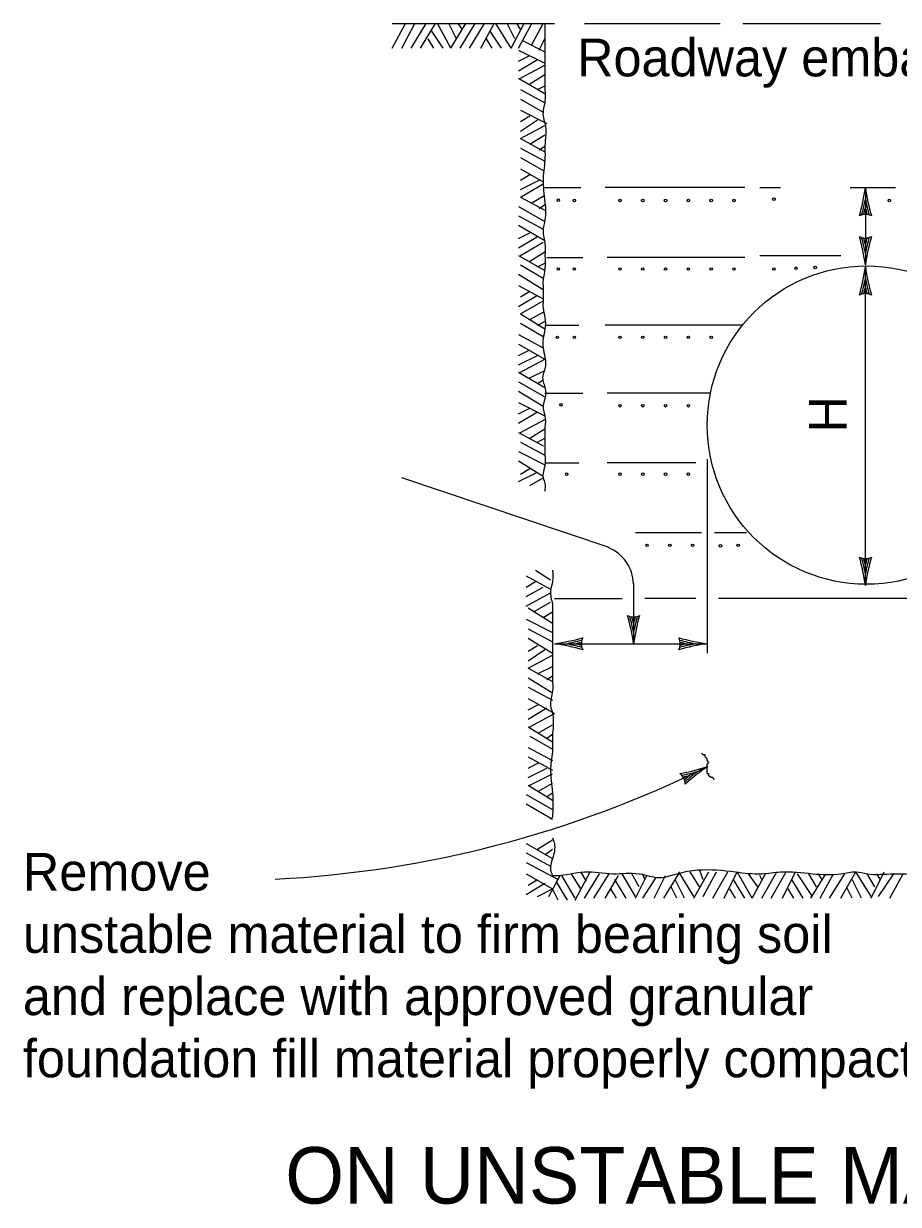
# Model space of a CAD drawing. Extents: x 0 to 390, y 0 to 265.
# Drawn here: x 170.5 to 216.9, y 109.5 to 172.1 of the extents above; entities that cross this region are included whole.
import ezdxf

# ---------------------------------------------------------------- set-up
doc = ezdxf.new("R2010")
doc.units = 0
doc.layers.add('D_Details', color=7, linetype='Continuous')

msp = doc.modelspace()

# ---------------------------------------------------------------- linework, layer by layer
at = {"layer": 'D_Details'}
for p, q in [((190.054, 170.801), (190.754, 172.101)), ((190.054, 172.101), (198.154, 172.101)), ((190.554, 170.801), (191.254, 172.101)), ((191.054, 170.801), (191.854, 172.101)), ((191.554, 170.801), (192.354, 172.101)), ((192.754, 170.801), (192.154, 171.701)), ((193.154, 170.801), (192.454, 172.101)), ((193.454, 171.301), (193.054, 172.101)), ((193.154, 170.801), (193.954, 172.101)), ((193.754, 171.801), (193.554, 172.101)), ((193.654, 170.801), (194.454, 172.101)), ((194.154, 170.801), (194.954, 172.101)), ((194.754, 170.801), (195.454, 172.101)), ((195.854, 170.801), (195.254, 171.701)), ((196.354, 170.801), (195.554, 172.101)), ((196.554, 171.301), (196.154, 172.101)), ((196.354, 170.801), (197.054, 172.101)), ((196.854, 171.801), (196.654, 172.101)), ((196.754, 170.801), (197.454, 172.101)), ((197.454, 171.001), (198.054, 172.101)), ((198.154, 172.101), (198.654, 172.101)), ((200.254, 172.101), (207.454, 172.101)), ((208.654, 172.101), (215.954, 172.101)), ((192.254, 170.801), (191.954, 171.301)), ((195.354, 170.801), (195.054, 171.301)), ((196.954, 171.201), (198.154, 170.601)), ((197.854, 170.701), (198.154, 171.301)), ((198.154, 171.201), (198.154, 171.201)), ((198.154, 171.201), (198.154, 171.201)), ((196.754, 170.701), (198.154, 170.001)), ((196.754, 170.101), (197.354, 170.401)), ((198.254, 171.001), (198.254, 171.001)), ((196.754, 169.601), (197.754, 170.201)), ((196.854, 169.201), (198.154, 169.901)), ((196.754, 169.201), (198.154, 168.401)), ((197.354, 168.901), (198.154, 169.401)), ((196.854, 168.601), (198.154, 167.901)), ((197.754, 168.601), (198.154, 168.801)), ((196.854, 168.101), (198.054, 167.401)), ((196.854, 167.501), (198.254, 166.801)), ((196.854, 166.901), (197.354, 167.201)), ((196.854, 166.401), (197.754, 167.001)), ((196.854, 166.001), (198.154, 166.701)), ((196.854, 166.001), (198.154, 165.301)), ((197.354, 165.701), (198.154, 166.201)), ((196.854, 165.501), (198.154, 164.801)), ((197.854, 165.401), (198.154, 165.601)), ((196.854, 165.001), (198.054, 164.301)), ((196.854, 164.401), (198.054, 163.701)), ((196.854, 163.801), (197.354, 164.101)), ((196.854, 163.301), (197.854, 163.801)), ((196.854, 162.901), (198.054, 163.601)), ((196.854, 162.901), (198.154, 162.201)), ((197.454, 162.601), (198.154, 163.001)), ((198.154, 163.401), (200.054, 163.401)), ((208.754, 163.401), (201.354, 163.401)), ((209.554, 163.401), (210.654, 163.401)), ((214.354, 163.401), (216.754, 163.401)), ((215.154, 163.401), (215.154, 159.301)), ((196.754, 162.401), (198.154, 161.601)), ((197.854, 162.301), (198.154, 162.501)), ((196.754, 161.901), (198.054, 161.201)), ((198.154, 162.201), (198.154, 162.201)), ((198.154, 162.201), (198.154, 162.201)), ((196.754, 161.401), (198.154, 160.601)), ((196.754, 160.701), (197.354, 161.001)), ((196.754, 160.201), (197.754, 160.801)), ((196.854, 159.801), (198.054, 160.501)), ((196.754, 159.801), (198.154, 159.001)), ((197.354, 159.501), (198.154, 160.001)), ((209.554, 159.801), (213.854, 159.801)), ((196.854, 159.301), (198.054, 158.601)), ((197.754, 159.201), (198.154, 159.401)), ((198.254, 159.701), (200.154, 159.701)), ((208.754, 159.701), (201.454, 159.701)), ((215.154, 142.301), (215.154, 159.201)), ((196.754, 158.801), (198.054, 158.001)), ((196.754, 158.201), (198.054, 157.501)), ((196.854, 157.601), (197.354, 157.901)), ((196.754, 157.101), (197.754, 157.701)), ((196.854, 156.701), (198.054, 157.401)), ((196.854, 156.701), (198.154, 155.901)), ((197.354, 156.401), (198.054, 156.801)), ((196.854, 156.201), (198.054, 155.501)), ((197.754, 156.101), (198.154, 156.301)), ((198.154, 156.101), (199.954, 156.101)), ((208.654, 156.101), (201.354, 156.101)), ((196.754, 155.601), (198.054, 154.901)), ((196.754, 155.101), (198.154, 154.301)), ((196.754, 154.501), (197.354, 154.801)), ((196.754, 154.001), (197.754, 154.501)), ((196.854, 153.601), (198.154, 154.301)), ((196.754, 153.601), (198.154, 152.801)), ((197.354, 153.301), (198.154, 153.701)), ((196.754, 153.101), (198.154, 152.301)), ((197.754, 153.001), (198.054, 153.201)), ((196.754, 152.601), (198.054, 151.801)), ((198.154, 152.801), (198.154, 152.801)), ((198.154, 152.501), (200.154, 152.501)), ((206.954, 152.501), (201.454, 152.501)), ((196.754, 152.001), (198.154, 151.301)), ((196.754, 151.401), (197.354, 151.701)), ((196.754, 150.901), (197.754, 151.501)), ((196.854, 150.401), (198.154, 151.101)), ((196.754, 150.401), (198.054, 149.701)), ((197.354, 150.101), (198.154, 150.601)), ((196.854, 149.901), (198.154, 149.201)), ((197.754, 149.901), (198.154, 150.101)), ((196.754, 149.401), (198.154, 148.701)), ((196.754, 148.901), (198.054, 148.101)), ((196.854, 148.201), (197.354, 148.501)), ((198.154, 148.801), (199.954, 148.801)), ((206.154, 148.801), (201.454, 148.801)), ((206.754, 149.001), (206.754, 138.701)), ((201.554, 144.301), (190.554, 148.001)), ((196.754, 147.801), (197.754, 148.301)), ((197.354, 147.601), (198.054, 148.001)), ((202.954, 145.101), (206.454, 145.101)), ((207.154, 145.101), (208.854, 145.101)), ((198.154, 143.501), (198.154, 143.501)), ((197.654, 143.101), (198.454, 142.601)), ((197.154, 142.801), (198.454, 142.101)), ((197.154, 142.201), (197.654, 142.501)), ((197.154, 141.701), (198.054, 142.201)), ((202.854, 142.401), (202.854, 139.201)), ((197.154, 141.201), (198.454, 141.901)), ((198.654, 141.601), (202.254, 141.601)), ((206.154, 141.601), (203.454, 141.601)), ((232.154, 141.601), (207.354, 141.601)), ((197.254, 141.101), (198.554, 140.301)), ((197.554, 140.901), (198.454, 141.401)), ((197.154, 140.501), (198.554, 139.801)), ((198.054, 140.601), (198.554, 140.901)), ((198.554, 140.501), (198.554, 140.501)), ((197.254, 140.001), (198.554, 139.301)), ((198.654, 140.301), (198.654, 140.301)), ((197.254, 139.501), (198.554, 138.701)), ((197.254, 138.801), (197.754, 139.101)), ((198.654, 139.201), (206.754, 139.201)), ((197.254, 138.301), (198.154, 138.901)), ((197.254, 137.901), (198.554, 138.601)), ((197.254, 137.901), (198.554, 137.201)), ((197.754, 137.601), (198.554, 138.001)), ((197.254, 137.401), (198.554, 136.601)), ((198.254, 137.301), (198.554, 137.501)), ((197.254, 136.901), (198.554, 136.201)), ((197.254, 136.301), (198.654, 135.501)), ((197.254, 135.701), (197.854, 136.001)), ((197.254, 135.201), (198.254, 135.801)), ((197.354, 134.801), (198.654, 135.501)), ((197.254, 134.801), (198.554, 134.001)), ((197.854, 134.501), (198.554, 134.901)), ((197.354, 134.301), (198.554, 133.601)), ((198.254, 134.201), (198.554, 134.401)), ((197.254, 133.701), (198.554, 133.001)), ((197.254, 133.201), (198.554, 132.501)), ((197.254, 132.601), (197.854, 132.901)), ((197.254, 132.101), (198.254, 132.601)), ((197.354, 131.701), (198.554, 132.301)), ((197.254, 131.701), (198.554, 130.901)), ((197.854, 131.401), (198.554, 131.801)), ((197.154, 131.201), (198.554, 130.401)), ((198.254, 131.101), (198.554, 131.301)), ((198.554, 131.001), (198.554, 131.001)), ((197.154, 130.701), (198.554, 129.901)), ((198.554, 130.001), (198.454, 129.901)), ((197.154, 128.601), (198.554, 127.801)), ((197.754, 128.301), (198.554, 128.801)), ((197.154, 128.101), (198.454, 127.401)), ((198.154, 128.001), (198.554, 128.301)), ((197.154, 127.601), (198.854, 126.701)), ((206.554, 126.701), (206.354, 127.201)), ((197.154, 127.001), (198.554, 126.201)), ((197.254, 126.401), (197.754, 126.701)), ((198.354, 125.801), (198.954, 126.901)), ((199.354, 125.601), (198.754, 126.601)), ((199.754, 125.701), (199.054, 126.901)), ((200.054, 126.201), (199.554, 127.001)), ((199.754, 125.601), (200.554, 127.101)), ((200.354, 126.601), (200.054, 127.101)), ((200.254, 125.701), (201.054, 127.001)), ((200.554, 127.101), (200.554, 127.101)), ((200.754, 125.701), (201.554, 127.001)), ((201.354, 125.701), (202.054, 126.901)), ((202.454, 125.701), (201.854, 126.701)), ((202.954, 125.801), (202.254, 127.001)), ((203.154, 126.301), (202.754, 127.001)), ((202.954, 125.701), (203.554, 126.901)), ((203.454, 126.701), (203.354, 127.001)), ((203.354, 125.701), (204.054, 126.801)), ((203.954, 125.701), (204.554, 126.901)), ((204.454, 125.701), (205.254, 127.001)), ((205.554, 125.701), (205.054, 126.701)), ((206.054, 125.801), (205.254, 127.101)), ((206.354, 126.301), (205.854, 127.101)), ((206.054, 125.701), (206.854, 127.101)), ((206.554, 125.801), (207.254, 127.101)), ((207.054, 125.701), (207.854, 127.101)), ((207.654, 125.701), (208.354, 127.101)), ((208.754, 125.701), (208.154, 126.701)), ((209.154, 125.701), (208.354, 127.101)), ((209.454, 126.301), (208.954, 127.001)), ((209.154, 125.701), (209.854, 127.001)), ((209.654, 126.701), (209.554, 126.901)), ((209.654, 125.701), (210.454, 127.101)), ((209.954, 127.101), (209.954, 127.101)), ((210.154, 125.701), (210.954, 127.101)), ((210.754, 125.701), (211.454, 127.101)), ((211.854, 125.701), (211.254, 126.701)), ((212.354, 125.801), (211.554, 127.001)), ((212.554, 126.301), (212.154, 127.001)), ((212.254, 125.701), (213.054, 127.001)), ((212.854, 126.701), (212.654, 127.001)), ((212.754, 125.701), (213.454, 127.001)), ((213.254, 125.701), (214.054, 127.001)), ((213.854, 125.701), (214.654, 127.101)), ((214.954, 125.701), (214.454, 126.701)), ((215.454, 125.801), (214.654, 127.101)), ((215.654, 126.301), (215.254, 127.001)), ((215.454, 125.701), (216.154, 127.101)), ((215.954, 126.701), (215.754, 127.001)), ((215.854, 125.801), (216.654, 127.001)), ((216.454, 125.701), (217.154, 127.001)), ((197.154, 125.901), (198.154, 126.501)), ((197.754, 125.801), (198.554, 126.201)), ((198.854, 125.601), (198.554, 126.201)), ((201.954, 125.701), (201.654, 126.201)), ((205.154, 125.701), (204.854, 126.301)), ((208.254, 125.701), (207.954, 126.201)), ((211.354, 125.701), (211.054, 126.201)), ((214.454, 125.701), (214.154, 126.301))]:
    msp.add_line(p, q, dxfattribs=at)
msp.add_lwpolyline([(207.154, 132.001), (207.054, 132.101), (206.954, 132.101), (206.854, 132.201), (206.854, 132.301), (206.754, 132.301), (206.754, 132.401), (206.754, 132.501), (206.754, 132.601), (206.754, 132.701), (206.754, 132.801), (206.854, 132.901), (206.754, 133.001), (206.754, 133.101), (206.654, 133.201), (206.654, 133.301), (206.554, 133.301), (206.454, 133.401)], dxfattribs=at)
for centre, radius in [((198.86, 162.738), 0.0674), ((199.714, 162.714), 0.0674), ((202.133, 162.714), 0.0674), ((203.342, 162.714), 0.0674), ((204.552, 162.714), 0.0674), ((205.761, 162.714), 0.0674), ((206.971, 162.714), 0.0674), ((208.181, 162.714), 0.0674), ((210.3, 162.789), 0.0674), ((216.422, 162.714), 0.0674), ((198.86, 159.086), 0.0674), ((199.714, 159.086), 0.0674), ((202.133, 159.086), 0.0674), ((203.342, 159.086), 0.0674), ((204.552, 159.086), 0.0674), ((205.761, 159.086), 0.0674), ((215.21, 150.802), 8.447), ((206.971, 159.086), 0.0674), ((208.181, 159.086), 0.0674), ((210.3, 159.086), 0.0674), ((211.472, 159.123), 0.0674), ((212.494, 159.161), 0.0674), ((198.812, 155.457), 0.0674), ((199.714, 155.457), 0.0674), ((202.133, 155.457), 0.0674), ((203.342, 155.457), 0.0674), ((204.552, 155.457), 0.0674), ((205.761, 155.457), 0.0674), ((206.971, 155.457), 0.0674), ((199.002, 151.876), 0.0674), ((202.133, 151.829), 0.0674), ((203.342, 151.829), 0.0674), ((204.552, 151.829), 0.0674), ((205.761, 151.829), 0.0674), ((199.302, 148.2), 0.0674), ((202.133, 148.2), 0.0674), ((203.342, 148.2), 0.0674), ((204.552, 148.2), 0.0674), ((205.761, 148.2), 0.0674), ((203.567, 144.421), 0.0674), ((204.777, 144.421), 0.0674), ((205.986, 144.421), 0.0674), ((207.467, 144.394), 0.0674), ((208.405, 144.421), 0.0674)]:
    msp.add_circle(centre, radius, dxfattribs=at)
for centre, radius, start, end in [((204.013, 164.967), 11.25, 344.18653, 352), ((226.294, 164.967), 11.25, 188, 195.81169), ((204.013, 164.967), 11.35, 344.56992, 348.99901), ((204.013, 164.967), 11.45, 344.82908, 346.64064), ((226.294, 164.967), 11.35, 191.00099, 195.43008), ((226.294, 164.967), 11.45, 193.35937, 195.17092), ((215.154, 161.277), 0.699, 63.215, 116.78499), ((204.013, 157.735), 11.25, 8, 15.81169), ((215.154, 161.425), 0.699, 243.215, 296.78499), ((204.013, 157.735), 11.35, 11.00099, 15.43008), ((204.013, 157.735), 11.45, 13.35937, 15.17092), ((226.294, 157.735), 11.35, 164.56992, 168.99901), ((226.294, 157.735), 11.25, 164.18653, 172), ((226.294, 157.735), 11.45, 164.82908, 166.64064), ((204.013, 160.767), 11.25, 344.18653, 352), ((226.294, 160.767), 11.25, 188, 195.81169), ((204.013, 160.767), 11.35, 344.56992, 348.99901), ((226.294, 160.767), 11.35, 191.00099, 195.43008), ((204.013, 160.767), 11.45, 344.82908, 346.64064), ((226.294, 160.767), 11.45, 193.35937, 195.17092), ((215.154, 157.077), 0.699, 63.215, 116.78499), ((200.683, 142.302), 2.171, 1.93194, 67.6808), ((204.013, 140.735), 11.25, 8, 15.81169), ((215.154, 144.425), 0.699, 243.215, 296.78499), ((204.013, 140.735), 11.35, 11.00099, 15.43008), ((204.013, 140.735), 11.45, 13.35937, 15.17092), ((226.294, 140.735), 11.35, 164.56992, 168.99901), ((226.294, 140.735), 11.25, 164.18653, 172), ((226.294, 140.735), 11.45, 164.82908, 166.64064), ((191.713, 137.635), 11.25, 8, 15.81169), ((202.854, 141.325), 0.699, 243.215, 296.78499), ((191.713, 137.635), 11.35, 11.00099, 15.43008), ((191.713, 137.635), 11.45, 13.35937, 15.17092), ((213.994, 137.635), 11.35, 164.56992, 168.99901), ((213.994, 137.635), 11.25, 164.18653, 172), ((213.994, 137.635), 11.45, 164.82908, 166.64064), ((197.088, 150.341), 11.25, 278, 285.81169), ((197.088, 128.06), 11.25, 74.18653, 82), ((197.088, 150.341), 11.35, 281.00099, 285.43008), ((197.088, 128.06), 11.35, 74.56992, 78.99901), ((197.088, 150.341), 11.45, 283.35937, 285.17092), ((197.088, 128.06), 11.45, 74.82908, 76.64064), ((200.778, 139.201), 0.699, 153.215, 206.78499), ((208.319, 150.341), 11.25, 254.18653, 262), ((204.63, 139.201), 0.699, 333.215, 26.78499), ((208.319, 128.06), 11.25, 98, 105.81169), ((208.319, 150.341), 11.35, 254.56992, 258.99901), ((208.319, 128.06), 11.35, 101.00099, 105.43008), ((208.319, 150.341), 11.45, 254.82908, 256.64064), ((208.319, 128.06), 11.45, 103.35937, 105.17092), ((180.922, 184.98), 58.338, 272.87415, 296.32811), ((203.258, 143.373), 11.25, 280.51464, 288.32811), ((204.892, 131.751), 0.699, 359.54312, 53.11311), ((203.258, 143.373), 11.35, 280.89804, 285.32712), ((203.258, 143.373), 11.45, 281.15719, 282.96875), ((213.14, 123.403), 11.45, 129.68748, 131.49904), ((213.14, 123.403), 11.35, 127.32911, 131.75819), ((213.14, 123.403), 11.25, 124.32811, 132.1398)]:
    msp.add_arc(centre, radius, start, end, dxfattribs=at)
for points in [[(198.154, 172.101), (198.154, 171.401), (198.154, 170.401), (198.154, 169.801), (198.154, 169.101), (198.154, 168.601), (198.154, 168.001), (198.054, 167.201), (198.154, 166.801), (198.154, 165.601), (198.154, 165.001), (198.054, 163.901), (198.154, 162.601), (198.154, 161.701), (198.054, 161.101), (198.154, 160.401), (198.154, 159.801), (198.154, 159.101), (198.054, 158.501), (198.054, 158.101)], [(198.054, 158.101), (198.054, 157.801), (198.054, 157.401), (198.054, 157.001), (198.154, 156.501), (198.154, 155.901), (198.054, 155.401), (198.054, 154.901), (198.154, 154.401), (198.154, 153.801), (198.054, 153.501), (198.054, 153.101), (198.154, 152.801), (198.154, 152.201), (198.054, 151.701), (198.154, 151.301), (198.154, 150.701), (198.154, 150.201), (198.154, 150.001), (198.154, 149.601), (198.154, 149.201), (198.154, 148.701), (198.054, 148.001), (198.154, 147.701), (198.154, 147.401), (198.154, 147.301)], [(198.554, 143.101), (198.554, 142.501), (198.454, 142.001), (198.554, 141.301)], [(198.554, 141.301), (198.554, 140.101), (198.554, 139.101), (198.554, 138.501), (198.554, 137.801), (198.554, 137.301), (198.554, 136.701), (198.454, 135.901), (198.554, 135.501), (198.554, 134.301), (198.554, 133.601), (198.454, 132.601), (198.554, 131.301), (198.554, 130.001)], [(198.554, 128.901), (198.654, 128.601), (198.554, 127.801), (198.454, 127.201), (198.554, 126.901)], [(198.554, 126.901), (198.754, 126.901), (200.254, 127.101), (201.754, 127.001), (203.154, 127.001), (204.254, 126.801), (205.154, 127.001), (206.254, 127.201), (208.254, 127.101), (209.654, 127.001), (210.654, 127.101), (212.354, 127.001), (213.854, 127.001), (214.654, 127.101), (215.254, 127.001), (216.654, 127.001), (219.254, 127.001), (220.554, 127.301), (222.754, 127.201), (224.554, 127.001), (226.154, 126.901), (228.054, 127.001), (229.654, 127.001), (231.454, 127.001), (232.454, 127.001)]]:
    msp.add_spline(points, degree=3, dxfattribs=at)

# ---------------------------------------------------------------- texts
for s, height, p in [('Roadway embankment', 2, (199.857, 169.302)), ('Remove', 2, (170.457, 126.102)), ('unstable material to firm bearing soil', 2, (170.457, 122.802)), ('and replace with approved granular', 2, (170.457, 119.502)), ('foundation fill material properly compacted.', 2, (170.457, 116.202)), ('ON UNSTABLE MATERIAL', 3, (184.374, 109.502))]:
    msp.add_text(s, height=height, dxfattribs=at).set_placement(p)
msp.add_text('H', height=2, rotation=90, dxfattribs=at).set_placement((214.157, 150.402))

doc.saveas('drawing.dxf')
